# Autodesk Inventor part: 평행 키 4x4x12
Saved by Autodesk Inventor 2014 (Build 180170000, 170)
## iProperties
Created: 2026-08
Part Number: 평행 키 4x4x12
Material: 강철, 연강
Document SubType Name: Modeling
Designer: dg
Density: 7.86 g/cm^3
Appearance: 강철
Mass: 1.38739 g
Surface Area: 1.94869 cm^2
Volume: 0.176513 cm^3
Author: jhkim
Description: 키 및 해당 키홈
Creation Date: 2026-07-31
Sending System: Autodesk Inventor 2027
Preprocessor: ST-DEVELOPER v20.1
Author: dg
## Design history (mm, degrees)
node "평행 키 4x4x121"
body "Solid1"
node "기준1"
